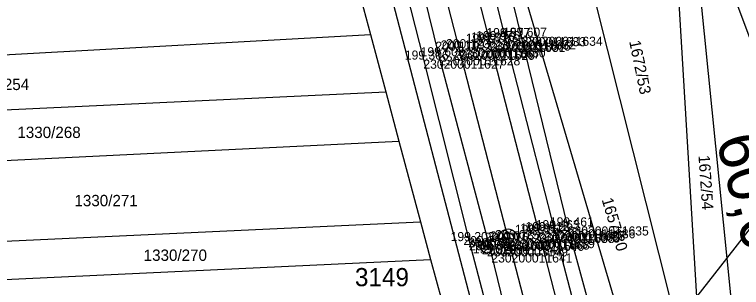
# Model space of a CAD drawing. Extents: x -563148 to -561712, y -1182311 to -1179502.
# Drawn here: x -562432.1 to -562336.1, y -1182154.9 to -1182118.9 of the extents above; entities that cross this region are included whole.
import ezdxf

# ---------------------------------------------------------------- set-up
doc = ezdxf.new("R2010")
doc.units = 0
for name, color, linetype in [('Vrstva 1', 7, 'Continuous'), ('Vrstva 4', 7, 'Continuous'), ('Vrstva 49', 7, 'Continuous'), ('Vrstva 53', 7, 'Continuous'), ('Vrstva 55', 7, 'Continuous'), ('Vrstva 57', 7, 'Continuous'), ('Vrstva 60', 7, 'Continuous'), ('Vrstva 61', 7, 'Continuous'), ('Vrstva 63', 7, 'Continuous'), ('Vrstva 7', 7, 'Continuous')]:
    doc.layers.add(name, color=color, linetype=linetype)

msp = doc.modelspace()

# ---------------------------------------------------------------- linework, layer by layer
at = {"layer": 'Vrstva 1'}
for points in [[(-562431.456, -1181882.158), (-562425.093, -1181906.771), (-562419.091, -1181930.016), (-562412.913, -1181953.965), (-562405.427, -1181982.918), (-562399.924, -1182004.215), (-562394.072, -1182026.888), (-562387.874, -1182050.84), (-562381.86, -1182074.092), (-562375.538, -1182098.521), (-562369.352, -1182122.433), (-562362.844, -1182147.635), (-562356.836, -1182170.919), (-562350.524, -1182195.336)], [(-562435.353, -1181883.455), (-562429.043, -1181907.884), (-562423.025, -1181931.202), (-562416.86, -1181955.033), (-562409.363, -1181984.042), (-562403.855, -1182005.364), (-562398.009, -1182028.011), (-562391.856, -1182051.875), (-562385.852, -1182075.188), (-562379.546, -1182099.541), (-562373.358, -1182123.485), (-562366.843, -1182148.681), (-562360.825, -1182171.976), (-562354.524, -1182196.409)]]:
    msp.add_lwpolyline(points, dxfattribs=at)
at = {"layer": 'Vrstva 4'}
for points in [[(-562356.597, -1182197.058), (-562363.671, -1182172.63), (-562369.111, -1182150.394), (-562376.003, -1182124.384), (-562381.959, -1182100.171), (-562388.242, -1182075.655), (-562394.258, -1182052.529), (-562401.091, -1182025.773), (-562406.12, -1182006.052), (-562411.703, -1181984.696), (-562419.188, -1181956.156), (-562425.491, -1181931.882), (-562431.354, -1181908.293), (-562438.222, -1181883.645), (-562444.124, -1181860.119), (-562450.397, -1181835.425), (-562455.984, -1181813.76), (-562461.844, -1181791.501), (-562470.013, -1181759.746), (-562475.447, -1181735.97), (-562481.267, -1181709.546), (-562485.292, -1181688.623), (-562489.631, -1181662.779), (-562492.854, -1181639.283)], [(-562429.083, -1181881.427), (-562423.039, -1181906.026), (-562416.991, -1181929.289), (-562410.946, -1181952.751), (-562403.313, -1181982.397), (-562397.583, -1182003.414), (-562392.555, -1182023.727), (-562385.634, -1182050.403), (-562379.578, -1182073.569), (-562373.303, -1182097.775), (-562367.317, -1182121.855), (-562360.795, -1182147.202), (-562354.718, -1182170.426), (-562348.388, -1182194.775)]]:
    msp.add_lwpolyline(points, dxfattribs=at)
at = {"layer": 'Vrstva 49'}
for points in [[(-562356.597, -1182197.058), (-562363.671, -1182172.63), (-562369.111, -1182150.394), (-562376.003, -1182124.384), (-562381.959, -1182100.171), (-562388.242, -1182075.655), (-562394.258, -1182052.529), (-562401.091, -1182025.773), (-562406.12, -1182006.052), (-562411.703, -1181984.696), (-562419.188, -1181956.156), (-562425.491, -1181931.882), (-562431.354, -1181908.293), (-562438.222, -1181883.645), (-562444.124, -1181860.119), (-562450.397, -1181835.425), (-562455.984, -1181813.76), (-562461.844, -1181791.501), (-562470.013, -1181759.746), (-562475.447, -1181735.97), (-562481.267, -1181709.546), (-562485.292, -1181688.623), (-562489.631, -1181662.779), (-562492.854, -1181639.283)], [(-562348.388, -1182194.775), (-562346.233, -1182193.909), (-562352.64, -1182170.226), (-562359.021, -1182146.828), (-562365.116, -1182121.8), (-562371.268, -1182096.806), (-562377.938, -1182072.997), (-562383.189, -1182049.641), (-562389.659, -1182023.356), (-562394.989, -1182002.824), (-562400.393, -1181981.55), (-562407.655, -1181951.839), (-562413.753, -1181928.351), (-562419.93, -1181905.004), (-562426.042, -1181880.285)], [(-562429.083, -1181881.427), (-562423.039, -1181906.026), (-562416.991, -1181929.289), (-562410.946, -1181952.751), (-562403.313, -1181982.397), (-562397.583, -1182003.414), (-562392.555, -1182023.727), (-562385.634, -1182050.403), (-562379.578, -1182073.569), (-562373.303, -1182097.775), (-562367.317, -1182121.855), (-562360.795, -1182147.202), (-562354.718, -1182170.426), (-562348.388, -1182194.775)], [(-562439.741, -1181884.96), (-562433.646, -1181909.277), (-562427.61, -1181932.656), (-562421.237, -1181957.617), (-562414.263, -1181985.119), (-562408.778, -1182006.666), (-562403.486, -1182026.149), (-562396.951, -1182053.474), (-562390.332, -1182076.348), (-562384.199, -1182100.797), (-562378.1, -1182124.825), (-562372.04, -1182148.774), (-562365.699, -1182172.919), (-562358.847, -1182197.091), (-562356.597, -1182197.058)]]:
    msp.add_lwpolyline(points, dxfattribs=at)
at = {"layer": 'Vrstva 53'}
for p, q in [((-562341.98, -1182156.11), (-562344.61, -1182112.38)), ((-562356.42, -1182113.03), (-562344.71, -1182159.58)), ((-562364.45, -1182184.72), (-562382.44, -1182115.94)), ((-562364.96, -1182115.6), (-562344.91, -1182183.41))]:
    msp.add_line(p, q, dxfattribs=at)
at = {"layer": 'Vrstva 55'}
for p, q in [((-562343.17, -1182099.99), (-562333.43, -1182126.19)), ((-562343.17, -1182099.99), (-562338.01, -1182151.05)), ((-562386.33, -1182116.89), (-562385.09, -1182121.5)), ((-562477.19, -1182126.62), (-562385.09, -1182121.5)), ((-562385.09, -1182121.5), (-562383.06, -1182129.08)), ((-562338.01, -1182151.05), (-562318.91, -1182126.7)), ((-562470.02, -1182133.14), (-562383.06, -1182129.08)), ((-562383.06, -1182129.08), (-562381.32, -1182135.57)), ((-562459.6, -1182139.39), (-562381.32, -1182135.57)), ((-562381.32, -1182135.57), (-562378.46, -1182146.24)), ((-562458.82, -1182149.95), (-562378.46, -1182146.24)), ((-562378.46, -1182146.24), (-562377.14, -1182151.18)), ((-562450, -1182154.61), (-562377.14, -1182151.18)), ((-562377.14, -1182151.18), (-562375.67, -1182156.66)), ((-562341.98, -1182156.11), (-562338.01, -1182151.05)), ((-562338.01, -1182151.05), (-562337.16, -1182159.49))]:
    msp.add_line(p, q, dxfattribs=at)
at = {"layer": 'Vrstva 60'}
for p, q in [((-562367.317, -1182121.855), (-562367.317, -1182121.855)), ((-562365.116, -1182121.8), (-562365.116, -1182121.8)), ((-562370.047, -1182122.614), (-562370.047, -1182122.614)), ((-562369.352, -1182122.433), (-562369.352, -1182122.433)), ((-562368.657, -1182122.253), (-562368.657, -1182122.253)), ((-562374.059, -1182123.654), (-562374.059, -1182123.654)), ((-562373.358, -1182123.485), (-562373.358, -1182123.485)), ((-562372.657, -1182123.316), (-562372.657, -1182123.316)), ((-562378.1, -1182124.825), (-562378.1, -1182124.825)), ((-562376.003, -1182124.384), (-562376.003, -1182124.384)), ((-562359.021, -1182146.828), (-562359.021, -1182146.828)), ((-562363.542, -1182147.82), (-562363.542, -1182147.82)), ((-562362.844, -1182147.635), (-562362.844, -1182147.635)), ((-562362.146, -1182147.45), (-562362.146, -1182147.45)), ((-562360.795, -1182147.202), (-562360.795, -1182147.202)), ((-562372.04, -1182148.774), (-562372.04, -1182148.774)), ((-562367.539, -1182148.855), (-562367.539, -1182148.855)), ((-562366.843, -1182148.681), (-562366.843, -1182148.681)), ((-562366.148, -1182148.507), (-562366.148, -1182148.507)), ((-562370.361, -1182149.302), (-562370.361, -1182149.302)), ((-562369.703, -1182149.592), (-562369.703, -1182149.592)), ((-562369.111, -1182150.394), (-562369.111, -1182150.394))]:
    msp.add_line(p, q, dxfattribs=at)
at = {"layer": 'Vrstva 63'}
msp.add_line((-562369.753, -1182149.592), (-562369.653, -1182149.592), dxfattribs=at)
msp.add_circle((-562369.703, -1182149.592), 0.756, dxfattribs=at)
at = {"layer": 'Vrstva 7'}
msp.add_line((-562370.374, -1182149.254), (-562370.348, -1182149.35), dxfattribs=at)
for centre, radius in [((-562366.913, -1182148.41), 1.246), ((-562366.913, -1182148.41), 0.752), ((-562370.361, -1182149.302), 0.5)]:
    msp.add_circle(centre, radius, dxfattribs=at)

# ---------------------------------------------------------------- texts
at = {"layer": 'Vrstva 57'}
for s, rotation, p in [('1672/53', 281.64699, (-562350.91, -1182122.42)), ('1672/54', 273.90861, (-562341.75, -1182137.47)), ('1657/30', 286.50771, (-562354.55, -1182143.29))]:
    msp.add_text(s, height=1.5, rotation=rotation, dxfattribs=at).set_placement(p)
for s, p in [('1330/254', (-562438.56, -1182128.84)), ('1330/268', (-562431.75, -1182135.17)), ('1330/271', (-562424.21, -1182144.17)), ('1330/270', (-562415.06, -1182151.38))]:
    msp.add_text(s, height=1.5, dxfattribs=at).set_placement(p)
at = {"layer": 'Vrstva 60'}
for s, p in [('230200011633', (-562367.317, -1182123.055)), ('230200011634', (-562365.116, -1182123)), ('230200011631', (-562370.047, -1182123.814)), ('230200011666', (-562369.352, -1182123.633)), ('230200011632', (-562368.657, -1182123.453)), ('230200011629', (-562374.059, -1182124.854)), ('230200011667', (-562373.358, -1182124.685)), ('230200011630', (-562372.657, -1182124.516)), ('230200011627', (-562378.1, -1182126.025)), ('230200011628', (-562376.003, -1182125.584)), ('230200011635', (-562359.021, -1182148.028)), ('230200011638', (-562363.542, -1182149.02)), ('230200011669', (-562362.844, -1182148.835)), ('230200011637', (-562362.146, -1182148.65)), ('230200011636', (-562360.795, -1182148.402)), ('230200011643', (-562372.04, -1182149.974)), ('230200011640', (-562367.539, -1182150.055)), ('230200011668', (-562366.843, -1182149.881)), ('230200011639', (-562366.148, -1182149.707)), ('230200011642', (-562370.361, -1182150.502)), ('230200003149', (-562369.703, -1182150.792)), ('230200011641', (-562369.111, -1182151.594))]:
    msp.add_text(s, height=1.2, dxfattribs=at).set_placement(p)
at = {"layer": 'Vrstva 61'}
for s, p in [('199.976', (-562371.109, -1182122.253)), ('199.577', (-562369.769, -1182121.855)), ('199.607', (-562367.568, -1182121.8)), ('199.978', (-562372.501, -1182122.614)), ('199.976', (-562371.804, -1182122.433)), ('200.119', (-562376.513, -1182123.654)), ('200.119', (-562375.812, -1182123.485)), ('200.123', (-562375.109, -1182123.316)), ('199.306', (-562380.552, -1182124.825)), ('199.603', (-562378.455, -1182124.384)), ('199.463', (-562363.247, -1182147.202)), ('199.461', (-562361.378, -1182146.828)), ('199.915', (-562365.998, -1182147.82)), ('199.912', (-562365.292, -1182147.635)), ('199.912', (-562364.594, -1182147.45)), ('199.203', (-562374.492, -1182148.774)), ('200.016', (-562369.991, -1182148.855)), ('200.016', (-562369.295, -1182148.681)), ('200.025', (-562368.604, -1182148.507)), ('200.138', (-562372.815, -1182149.302)), ('200.135', (-562372.159, -1182149.592)), ('199.529', (-562371.565, -1182150.394))]:
    msp.add_text(s, height=1.2, dxfattribs=at).set_placement(p)
at = {"layer": 'Vrstva 63'}
msp.add_text('3149', height=2.4, dxfattribs=at).set_placement((-562387.139, -1182154.723))
at = {"layer": 'Vrstva 7'}
msp.add_text('60,0', height=6, rotation=284.48502, dxfattribs=at).set_placement((-562339.45, -1182135.353))

doc.saveas('drawing.dxf')
